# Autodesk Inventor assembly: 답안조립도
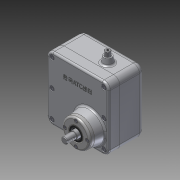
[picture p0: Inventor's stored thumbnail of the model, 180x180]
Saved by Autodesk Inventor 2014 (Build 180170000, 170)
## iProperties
Created: 2015-10
Part Number: 답안조립도
Document SubType Name: Assembly
Designer: Owner
Mass: 1071.35 g
Surface Area: 1352.07 cm^2
Volume: 278.053 cm^3
Density: 3.85303 g/cm^3
Author: Owner
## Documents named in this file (15)
- C:\Documents and Settings\Owner\바탕 화면\351007V1008\답안조립도.iam
- C:\Documents and Settings\Owner\바탕 화면\351007V1008\본체.ipt
- C:\Documents and Settings\Owner\바탕 화면\351007V1008\커버.ipt
- C:\Documents and Settings\Owner\바탕 화면\351007V1008\편심 축.ipt
- C:\Documents and Settings\Owner\바탕 화면\351007V1008\베어링 6002.ipt
- C:\Documents and Settings\Owner\바탕 화면\351007V1008\베어링 6001.ipt
- C:\Documents and Settings\Owner\바탕 화면\351007V1008\축 커버.ipt
- C:\Documents and Settings\Owner\바탕 화면\351007V1008\M3 x 0.5.ipt
- C:\Documents and Settings\Owner\바탕 화면\351007V1008\오일실 12 x 22.ipt
- C:\Documents and Settings\Owner\바탕 화면\351007V1008\로드 축.ipt
- C:\Documents and Settings\Owner\바탕 화면\351007V1008\오일실 15 x 25.ipt
- C:\Documents and Settings\Owner\바탕 화면\351007V1008\로드.ipt
- C:\Documents and Settings\Owner\바탕 화면\351007V1008\슬라이드.ipt
- C:\Documents and Settings\Owner\바탕 화면\351007V1008\가변 스프링.ipt
- C:\Documents and Settings\Owner\바탕 화면\351007V1008\M4 x 0.7.ipt
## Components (11 placed, 3 different names)
1. 가변 스프링:1
2. M3 x 0.5:1
3. M3 x 0.5:2
4. M3 x 0.5:3
5. M3 x 0.5:4
6. M4 x 0.7:1 — 각도:1
7. M4 x 0.7:2
8. M4 x 0.7:3
9. M4 x 0.7:4
10. M4 x 0.7:5
11. M4 x 0.7:6
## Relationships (1: Angle 1)
- 각도:1 [Angle]: M4 x 0.7:1
